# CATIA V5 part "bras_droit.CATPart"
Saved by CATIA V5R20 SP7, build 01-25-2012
Part number: bras_droit
Bounding box of the stored display mesh (mm): x -29.977 to 584.177, y -420 to 729.978, z 0 to 20
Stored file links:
  U:\IAO\thinkmotion catia2\bras_droit.CATPart
  U:\IAO\thinkmotion catia2\Ass_862_adubourgno.CATProduct
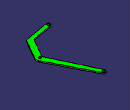
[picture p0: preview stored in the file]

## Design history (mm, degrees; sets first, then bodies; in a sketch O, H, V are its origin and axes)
Set1
  Plane1: linked copy from another document
  Point1 "J": linked copy from another document
  Point2 "M": linked copy from another document
  Point3 "A": linked copy from another document
  Point4 "C": linked copy from another document
  Point5 "F": linked copy from another document
Body1 (main body)
  Sketch1 on Plane1, origin (0, 0, 0), H (1, 0, 0), V (0, 1, 0)
    construction line L1 (524.226, 0) -> (594.6728, -40.6725)
    point P1 (524.226, 0)
    point P2 (594.6728, -40.6725)
    reference projected point E1 (524.226, 0) from Point1
    construction line L2 (350, 0) -> (524.226, 0)
    point P3 (350, 0)
    point P4 (524.226, 0)
    reference projected point E2 (350, 0) from Point2
    reference projected point E3 (524.226, 0) from Point1
    point P5 (594.6728, 40.6725)
    point P6 (524.226, 0)
    construction line L3 (524.226, 0) -> (594.6728, 40.6725)
    arc A1 centre (524.226, 0) radius 60 from (576.1875, -30) to (576.1875, 30) ccw
    point P7 (524.226, 0)
    point P8 (576.1875, -30)
    point P9 (576.1875, 30)
    reference projected point E4 (524.226, 0) from Point1
    line L4 (576.1875, -30) -> (390.8059, -351.0904)
    point P10 (576.1875, -30)
    reference projected point E5 (524.226, 0) from Point1
    construction line L5 (0, -390) -> (0, 700)
    point P11 (0, -390)
    point P12 (0, 700)
    reference projected point E8 (0, -390) from Point4
    reference projected point E9 (0, 700) from Point3
    line L6 (0, -420) -> (390.8059, -351.0904)
    point P13 (0, -420)
    reference projected point E10 (0, -390) from Point4
    line L7 (-14.298, -363.6264) -> (318.128, -305.0107)
    line L8 (494.226, 0) -> (318.128, -305.0107)
    point P15 (494.226, 0)
    reference projected point E11 (524.226, 0) from Point1
    arc A2 centre (0, -390) radius 30 from (-14.298, -363.6264) to (0, -420) ccw
    point P17 (0, -390)
    reference projected point E12 (0, -390) from Point4
    circle A3 centre (0, -390) radius 20
    point P20 (0, -390)
    reference projected point E13 (0, -390) from Point4
    circle A4 centre (524.226, 0) radius 20
    point P21 (524.226, 0)
    reference projected point E14 (524.226, 0) from Point1
    construction line L9 (200, 700) -> (524.226, 0)
    point P22 (200, 700)
    point P23 (524.226, 0)
    reference projected point E15 (524.226, 0) from Point1
    reference projected point E16 (200, 700) from Point5
    line L10 (576.1875, 30) -> (226.1616, 714.6823)
    point P24 (227.2218, 712.6086)
    axis line L11 (200, 700) -> (243.2893, 720.0508)
    point P25 (200, 700)
    reference projected point E17 (200, 700) from Point5
    reference projected point E18 (200, 700) from Point5
    line L12 (494.226, 0) -> (172.7782, 687.3914)
    point P27 (172.7782, 687.3914)
    reference projected point E19 (200, 700) from Point5
    arc A5 centre (200, 700) radius 30 from (226.1616, 714.6823) to (172.7782, 687.3914) ccw
    point P28 (200, 700)
    reference projected point E20 (200, 700) from Point5
    circle A6 centre (200, 700) radius 20
    point P31 (200, 700)
    reference projected point E21 (200, 700) from Point5
    distance E1 P1 = 0
    distance E2 P3 = 0
    distance E3 P4 = 0
    angle L2 L1 = 150
    distance E4 P7 = 0
    radius A1 = 60
    distance P10 E5 = 60
    angle L4 L1 = 90
    distance E8 P11 = 0
    distance E9 P12 = 0
    distance E10 P13 = 30
    angle L5 L6 = 80
    distance E11 P15 = 30
    angle L8 L2 = 120
    radius A2 = 30
    distance E12 P17 = 0
    distance L7 L6 = 58
    radius A3 = 20
    distance E13 P20 = 0
    radius A4 = 20
    distance E14 P21 = 0
    distance E15 P23 = 0
    distance E16 P22 = 0
    distance E17 P25 = 0
    angle L9 L11 = 90
    distance L11 P24 = 0
    distance E18 P24 = 30
    distance L11 P27 = 0
    distance E19 P27 = 30
    radius A5 = 30
    distance E20 P28 = 0
    radius A6 = 20
    distance E21 P31 = 0
    symmetry: P2 P5 L2, P1 P6 L2, L1 L3 L2
    coincidence: P8 L1, P9 L3, P10 L1, P13 L5, P15 L2, P13 L6, P24 L10, P27 L12, P8 P10
  Pad1: profile Sketch1, direction (0, 0, 1), length 20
